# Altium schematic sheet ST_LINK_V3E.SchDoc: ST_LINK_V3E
size A3; Date: Not used; ApprovedBy: Not used; CheckedBy: Not used; Author: Not used; CompanyName: STMicroelectronics; DrawnBy: Not used; Engineer: Not used; Organization: Not used; Address1: Not used; Address2: Not used; Address3: Not used; Address4: Not used; DocumentNumber: Not used; Revision: Not used; SheetNumber: 10; SheetTotal: 12
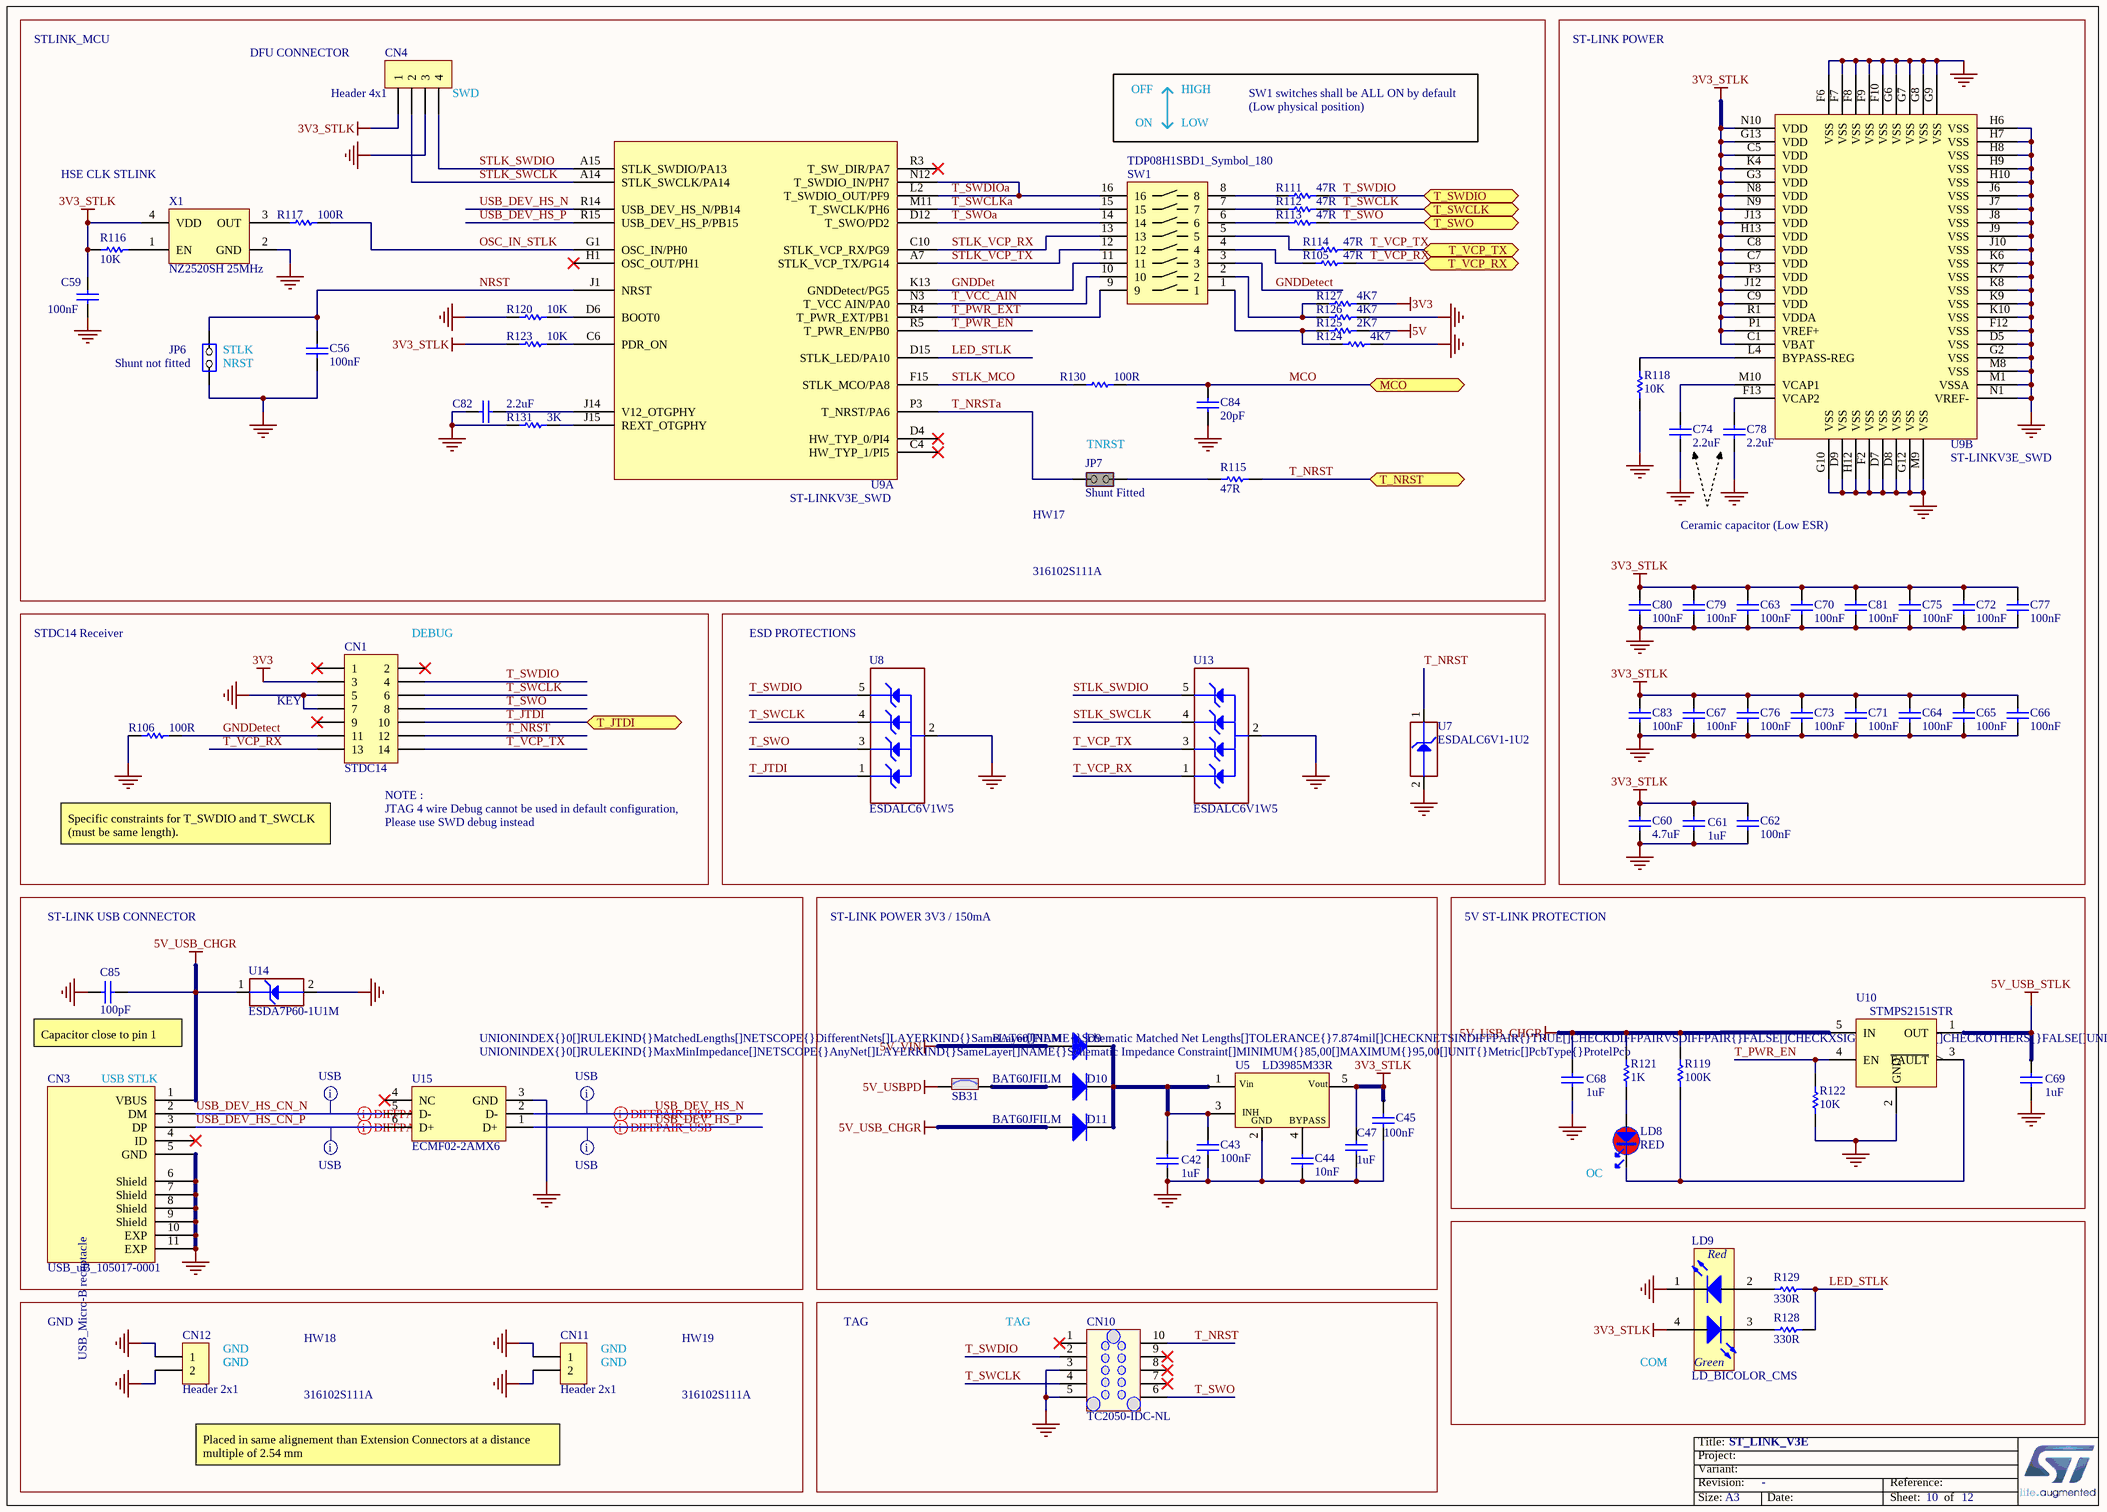
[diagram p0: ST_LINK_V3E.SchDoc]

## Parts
C42  value 1uF  [C0603]
C43  value 100nF  [C0402]
C44  value 10nF  [C0402]
C45  value 100nF  [C0402]
C47  value 1uF  [C0603]
C56  value 100nF  [C0402]
C59  value 100nF  [C0402]
C60  value 4.7uF  [C0603]
C61  value 1uF  [C0603]
C62  value 100nF  [C0402]
C63  value 100nF  [C0402]
C64  value 100nF  [C0402]
C65  value 100nF  [C0402]
C66  value 100nF  [C0402]
C67  value 100nF  [C0402]
C68  value 1uF  [C0603]
C69  value 1uF  [C0603]
C70  value 100nF  [C0402]
C71  value 100nF  [C0402]
C72  value 100nF  [C0402]
C73  value 100nF  [C0402]
C74  value 2.2uF  [C1206_H1P15]
C75  value 100nF  [C0402]
C76  value 100nF  [C0402]
C77  value 100nF  [C0402]
C78  value 2.2uF  [C1206_H1P15]
C79  value 100nF  [C0402]
C80  value 100nF  [C0402]
C81  value 100nF  [C0402]
C82  value 2.2uF  [C0603]
C83  value 100nF  [C0402]
C84  value 20pF  [C0402]
C85  value 100pF  [C0402]
CN1  value STDC14  [CON_STDC14_Receiver_MEDIUM]
CN3  value USB_uB_105017-0001  [CON_USBMICROB_MOLEX_105017-0001_H2P90]
CN4  value Header 4x1  [CON_SAMTEC_TSW-104-07-G-S]
CN10  value TC2050-IDC-NL  [CON_TAG-C_TC2050-IDC-NL]
CN11  Header 2x1  [CON_LYCONN_313102S141346]
CN12  Header 2x1  [CON_LYCONN_313102S141346]
D9  value BAT60JFILM  [DIO_SOD323]
D10  value BAT60JFILM  [DIO_SOD323]
D11  value BAT60JFILM  [DIO_SOD323]
HW17  value 316102S111A  (hidden comment: JUMPER_OPEN)
HW18  value 316102S111A  (hidden comment: JUMPER_OPEN)
HW19  value 316102S111A  (hidden comment: JUMPER_OPEN)
JP6  value Shunt not fitted  [CON_988-JIUBABA_313102S111116]  (hidden comment: Jumper_Header 2x1)
JP7  value Shunt Fitted  [CON_988-JIUBABA_313102S111116]  (hidden comment: Jumper_Header 2x1 Fitted)
LD8  value RED  [LED_0603_RED]
LD9  value LD_BICOLOR_CMS  [LED_BI-GR_HSMF-A201-A00J1]
R105  value 47R  [R0402]
R106  value 100R  [R0402]
R111  value 47R  [R0402]
R112  value 47R  [R0402]
R113  value 47R  [R0402]
R114  value 47R  [R0402]
R115  value 47R  [R0402]
R116  value 10K  [R0402]
R117  value 100R  [R0402]
R118  value 10K  [R0402]
R119  value 100K  [R0603]
R120  value 10K  [R0402]
R121  value 1K  [R0603]
R122  value 10K  [R0603]
R123  value 10K  [R0402]
R124  value 4K7  [R0402]
R125  value 2K7  [R0402]
R126  value 4K7  [R0402]
R127  value 4K7  [R0402]
R128  value 330R  [R0603]
R129  value 330R  [R0603]
R130  value 100R  [R0402]
R131  value 3K  [R0402]
SB31  SB_ON  [SOLDER-BRIDGE_R0603-0R]  (value not drawn)
SW1  value TDP08H1SBD1_Symbol_180  [SWI_C&K_TDP08H1SBD1]  (hidden comment: TDP08H1SBD1_180)
U5  value LD3985M33R  [REG_SOT23-5L]
U7  value ESDALC6V1-1U2  [ESD_ST0201]
U8  value ESDALC6V1W5  [ESD_SOT323-5L]
U9  value ST-LINKV3E_SWD  [ICC_UFBGA201_176+25_10X10_P065]  (parts A,B of 2)
U10  value STMPS2151STR  [MOS_SOT23-5L]
U13  value ESDALC6V1W5  [ESD_SOT323-5L]
U14  value ESDA7P60-1U1M  [ESD_QFN2_1P6X1_P125]
U15  value ECMF02-2AMX6  [ESD_QFN-6L_1P7X1P5_P050]
X1  value NZ2520SH 25MHz  [OSC_NDK_NZ2520SB_4P]  (hidden comment: OSCILLATOR_4_PINS)

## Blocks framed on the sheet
ESD PROTECTIONS: U7 U8 U13
ST-LINK POWER 3V3 / 150mA: C42-C45 C47 D9-D11 SB31 U5
COM: LD9 R128 R129

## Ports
MCO, T_JTDI, T_NRST, T_SWCLK, T_SWDIO, T_SWO, T_VCP_RX, T_VCP_TX

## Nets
3V3: CN1.3 R127.2
3V3_STLK: C45.2 C47.2 C59.2 C60.2 C61.2 C62.2 C63.2 C64.2 C65.2 C66.2 C67.2 C70.2 C71.2 C72.2 C73.2 C75.2 C76.2 C77.2 C79.2 C80.2 C81.2 C83.2 CN4.1 LD9.4(YellowGreen_anode) R116.1 R123.1 U5.5(Vout) U9.C1(VBAT) U9.C5(VDD) U9.C7(VDD) U9.C8(VDD) U9.C9(VDD) U9.F3(VDD) U9.G3(VDD) U9.G13(VDD) U9.H13(VDD) U9.J12(VDD) U9.J13(VDD) U9.K4(VDD) U9.N8(VDD) U9.N9(VDD) U9.N10(VDD) U9.P1(VREF+) U9.R1(VDDA) X1.4(VDD)
5V: R125.1
5V_USB_CHGR: C68.2 C85.2 CN3.1(VBUS) D11.1(A) R119.2 R121.2 U10.5(IN) U14.1(IO1)
5V_USB_STLK: C69.2 U10.1(OUT)
5V_USBPD: SB31.1
5V_VIN: D9.1(A)
GND: C42.1 C43.1 C44.1 C45.1 C47.1 C56.1 C59.1 C60.1 C61.1 C62.1 C63.1 C64.1 C65.1 C66.1 C67.1 C68.1 C69.1 C70.1 C71.1 C72.1 C73.1 C74.1 C75.1 C76.1 C77.1 C78.1 C79.1 C80.1 C81.1 C82.1 C83.1 C84.1 C85.1 CN1.5 CN1.7 CN3.5(GND) CN3.6(Shield) CN3.7(Shield) CN3.8(Shield) CN3.9(Shield) CN3.10(EXP) CN3.11(EXP) CN4.3 CN10.3 CN10.5 CN11.1 CN11.2 CN12.1 CN12.2 JP6.1(COMMON) LD9.1(RED_cathode) R106.1 R118.1 R120.1 R122.2 R124.1 R126.2 R131.1 U5.2(GND) U7.2(GND) U8.2(GND) U9.D5(VSS) U9.D7(VSS) U9.D8(VSS) U9.D9(VSS) U9.F2(VSS) U9.F6(VSS) U9.F7(VSS) U9.F8(VSS) U9.F9(VSS) U9.F10(VSS) U9.F12(VSS) U9.G2(VSS) U9.G6(VSS) U9.G7(VSS) U9.G8(VSS) U9.G9(VSS) U9.G10(VSS) U9.G12(VSS) U9.H6(VSS) U9.H7(VSS) U9.H8(VSS) U9.H9(VSS) U9.H10(VSS) U9.H12(VSS) U9.J6(VSS) U9.J7(VSS) U9.J8(VSS) U9.J9(VSS) U9.J10(VSS) U9.K6(VSS) U9.K7(VSS) U9.K8(VSS) U9.K9(VSS) U9.K10(VSS) U9.M1(VSSA) U9.M8(VSS) U9.M9(VSS) U9.N1(VREF-) U10.2(GND) U13.2(GND) U14.2(GND) U15.3(GND) X1.2(GND)
GNDDet: SW1.11 U9.K13(GNDDetect/PG5)
GNDDetect: CN1.11 R106.2 SW1.3
LED_STLK: R128.2 R129.2 U9.D15(STLK_LED/PA10)
MCO: C84.2 R130.2 ; port MCO
NRST: C56.2 JP6.2(NO) U9.J1(NRST)
OSC_IN_STLK: R117.2 U9.G1(OSC_IN/PH0)
STLK_MCO: R130.1 U9.F15(STLK_MCO/PA8)
STLK_SWCLK: CN4.2 U9.A14(STLK_SWCLK/PA14) U13.4(IO3)
STLK_SWDIO: CN4.4 U9.A15(STLK_SWDIO/PA13) U13.5(IO4)
STLK_VCP_RX: SW1.13 U9.C10(STLK_VCP_RX/PG9)
STLK_VCP_TX: SW1.12 U9.A7(STLK_VCP_TX/PG14)
T_JTDI: CN1.10 U8.1(IO1) ; port T_JTDI
T_NRST: CN1.12 CN10.10 R115.2 U7.1(IO1) ; port T_NRST
T_NRSTa: JP7.1(COMMON) U9.P3(T_NRST/PA6)
T_PWR_EN: R122.1 U9.R5(T_PWR_EN/PB0) U10.4(EN)
T_PWR_EXT: SW1.9 U9.R4(T_PWR_EXT/PB1)
T_SWCLK: CN1.6 CN10.4 R112.2 U8.4(IO3) ; port T_SWCLK
T_SWCLKa: SW1.15 U9.M11(T_SWCLK/PH6)
T_SWDIO: CN1.4 CN10.2 R111.2 U8.5(IO4) ; port T_SWDIO
T_SWDIOa: SW1.16 U9.L2(T_SWDIO_OUT/PF9) U9.N12(T_SWDIO_IN/PH7)
T_SWO: CN1.8 CN10.6 R113.2 U8.3(IO2) ; port T_SWO
T_SWOa: SW1.14 U9.D12(T_SWO/PD2)
T_VCC_AIN: SW1.10 U9.N3(T_VCC_AIN/PA0)
T_VCP_RX: CN1.13 R105.2 U13.1(IO1) ; port T_VCP_RX
T_VCP_TX: CN1.14 R114.2 U13.3(IO2) ; port T_VCP_TX
USB_DEV_HS_CN_N: CN3.2(DM) U15.5(D-)
USB_DEV_HS_CN_P: CN3.3(DP) U15.6(D+)
USB_DEV_HS_N: U9.R14(USB_DEV_HS_N/PB14) U15.2(D-)
USB_DEV_HS_P: U9.R15(USB_DEV_HS_P/PB15) U15.1(D+)
NetC42_2: C42.2 C43.2 D9.2(K) D10.2(K) D11.2(K) U5.1(Vin) U5.3(CE)
NetC44_2: C44.2 U5.4(BYPASS)
NetC74_2: C74.2 U9.M10(VCAP1)
NetC78_2: C78.2 U9.F13(VCAP2)
NetC82_2: C82.2 U9.J14(V12_OTGPHY)
NetD10_1: D10.1(A) SB31.2
NetJP7_2: JP7.2(NO) R115.1
NetLD8_1: LD8.1 R121.1
NetLD8_2: LD8.2 R119.1 U10.3(~{FAULT})
NetLD9_2: LD9.2(Red_anode) R129.1
NetLD9_3: LD9.3(YellowGreen_cathode) R128.1
NetR105_1: R105.1 SW1.4
NetR111_1: R111.1 SW1.8
NetR112_1: R112.1 SW1.7
NetR113_1: R113.1 SW1.6
NetR114_1: R114.1 SW1.5
NetR116_2: R116.2 X1.1(EN)
NetR117_1: R117.1 X1.3(OUT)
NetR118_2: R118.2 U9.L4(BYPASS-REG)
NetR120_2: R120.2 U9.D6(BOOT0)
NetR123_2: R123.2 U9.C6(PDR_ON)
NetR124_2: R124.2 R125.2 SW1.1
NetR126_1: R126.1 R127.1 SW1.2
NetR131_2: R131.2 U9.J15(REXT_OTGPHY)

Not connected (* = marked no-connect by the designer): CN1 1* 2* 9*; CN3 4(ID)*; CN10 1* 7* 8* 9*; U9 C4(HW_TYP_1/PI5)* D4(HW_TYP_0/PI4)* H1(OSC_OUT/PH1)* R3(T_SW_DIR/PA7)*; U15 4(NC)*

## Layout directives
differential pair; rule Impedance Constraint [Min = 85.00    Max = 95.00    ]: USB_DEV_HS_CN_N, USB_DEV_HS_CN_P, USB_DEV_HS_N, USB_DEV_HS_P
rule Undefined; rule Matched Net Lengths [Tolerance = 0.2mm]; rule Impedance Constraint [Min = 85.00    Max = 95.00    ]: USB_DEV_HS_CN_N, USB_DEV_HS_CN_P, USB_DEV_HS_N, USB_DEV_HS_P

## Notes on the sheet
- STLINK_MCU
- ST-LINK POWER
- DFU CONNECTOR
- (near CN4) SWD
- OFF
- HIGH
- SW1 switches shall be ALL ON by default
- (Low physical position)
- HSE CLK STLINK
- ON
- LOW
- (near JP6) STLK
- (near JP6) NRST
- (near JP7) TNRST
- Ceramic capacitor (Low ESR)
- STDC14 Receiver
- (near CN1) DEBUG
- (near CN1) KEY
- Specific constraints for T_SWDIO and T_SWCLK (must be same length).
- JTAG 4 wire Debug cannot be used in default configuration,
- Please use SWD debug instead
- (near CN1) NOTE :
- ST-LINK USB CONNECTOR
- 5V ST-LINK PROTECTION
- (near C85) Capacitor close to pin 1
- (near CN3) USB STLK
- (near LD8) OC
- GND
- TAG
- Placed in same alignement than Extension Connectors at a distance multiple of 2.54 mm

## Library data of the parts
C42 C47 C61 C68 C69 = MCD-00010: Capacitor, MLCC, 1uF, 16V, X5R, 10%, 0603, T=0,8mm; Manufacturer_Part_Number: CC0603KRX5R7BB105; Manufacturer: YAGEO; Provided_By: SUBCO
C43 C45 C56 C59 C62-C67 C70-C73 C75-C77 C79-C81 C83 = MCD-00102: Capacitor, MLCC, 100nF, 16V, X7R, 10%, 0402, T=0,5mm; Manufacturer_Part_Number: CC0402KRX7R7BB104; Manufacturer: YAGEO; Alternate_Manufacturer_Part_Number: GCM155R71C104KA55D; Alternate_Manufacturer: MURATA; Provided_By: SUBCO
C44 = MCD-00011: Capacitor, MLCC, 10nF, 16V, X7R, 10%, 0402, T=0.5mm; Manufacturer_Part_Number: CC0402KRX7R7BB103; Manufacturer: YAGEO; Provided_By: SUBCO
C60 = MCD-00009: Capacitor, MLCC, 4.7uF, 16V, X5R, 10%, 0603, T=0.8mm; Manufacturer_Part_Number: CC0603KRX5R7BB475; Manufacturer: YAGEO; Provided_By: SUBCO
C74 C78 = MCD-00008: Capacitor, MLCC, 2.2uF, 16V, X7R, 10%, 1206, T=1,15mm; Manufacturer_Part_Number: CC1206KKX7R7BB225; Manufacturer: YAGEO; Alternate_Manufacturer_Part_Number: C1206C225K4RAC; Alternate_Manufacturer: KEMET; Provided_By: SUBCO
C82 = MCD-00012: Capacitor, MLCC, 2.2uF, 10V, X5R, 10%, 0603, T=0,8mm; Manufacturer_Part_Number: CC0603KRX5R6BB225; Manufacturer: YAGEO; Alternate_Manufacturer_Part_Number: C0603C225K8PACTU; Alternate_Manufacturer: KEMET; Provided_By: SUBCO
C84 = MCD-00016: Capacitor, MLCC, 20pF, 50V, NPO, 5%, 0402, T=0,5mm; Manufacturer_Part_Number: CC0402JRNPO9BN200; Manufacturer: YAGEO; Provided_By: SUBCO
C85 = MCD-00205: Capacitor, MLCC, 100pF, 50V, NPO, 5%, 0402, T=0,5mm; Manufacturer_Part_Number: CC0402JRNPO9BN101; Manufacturer: YAGEO; Provided_By: SUBCO
CN1 = MCD-00592: Header 7x2, 1.27mm, Dual row, Straight, "STDC14_MEDIUM" : footprint compatible with FTSH-107-01-L-DV,-K,-A,-P,-ES (use "STDC14_BIG" to also be compatible with SHF-107-01-L-D-SM,-K); Part_Type: Connector; Manufacturer_Part_Number: FTSH-107-01-L-DV-K; Manufacturer: SAMTEC; Provided_By: SUBCO
CN3 = MCD-00028: USB-MICRO-B, 0.65mm, RA, SMT, Bottom Mount,; Manufacturer_Part_Number: 1050170001; Manufacturer: MOLEX; Part_Type: Connector; Provided_By: SUBCO
CN4 = MCD-00029: Header, 4x1, 2,54mm, VR, TH, Height 5.84mm/2.54mm; Manufacturer_Part_Number: TSW-104-07-x-S; Manufacturer: SAMTEC; Part_Type: Connector; Provided_By: SUBCO
CN10 = MCD-00031: Tag_Connector Header, 10x2, No legs; Manufacturer_Part_Number: TC2050-IDC-NL-FP; Manufacturer: TAG-CONNECT LLC; Provided_By: SUBCO
CN11 CN12 = MCD-01668: Header 2x1, 2.54mm, VR, TH, height 5.84mm/5.08 mm, height total 13.46 mm; Part_Type: Connector; Manufacturer_Part_Number: 313102S141346; Manufacturer: LYCONN; Provided_By: SUBCO
D9-D11 = MCD-00034: BAT60JFILM; Manufacturer: STMICROELECTRONICS; Part_Type: Diode; BMS_Part_Number: 9151097; Provided_By: SUBCO with ST control
HW17-HW19 = MCD-01849: Jumper, height 6mm, Black, 2.54mm, 3A, 20 mohm, open; Part_Type: Mechanical; Manufacturer: JIUBABA; Provided_By: SUBCO
JP6 = MCD-01660: Header 2x1, 2.54mm, VR, TH, height 6 mm / 3 mm, total 11.6mm - Shunt not Fitted by default; Part_Type: Connector; Manufacturer_Part_Number: 313102S111116; Manufacturer: JIUBABA; Provided_By: SUBCO
JP7 = MCD-01662: Header 2x1, 2.54mm, VR, TH, height 6 mm / 3 mm, total 11.6mm - Shunt Fitted by default; Part_Type: Connector; Manufacturer_Part_Number: 313102S111116; Manufacturer: JIUBABA; Provided_By: SUBCO
LD8 = MCD-00049: LED, Red, 0603; Manufacturer_Part_Number: 19-213-R6C-AP1Q2B/3T; Manufacturer: EVERLIGHT; Part_Type: Display; Provided_By: SUBCO
LD9 = MCD-00051: LED Bicolor; Part_Type: Display; Manufacturer_Part_Number: HSMF-A201-A00J1; Manufacturer: AVAGO TECHNOLOGIES; Alternate_Manufacturer_Part_Number: LE-RGW35280; Alternate_Manufacturer: EVERLUCK; Provided_By: SUBCO
R105 R111-R115 = MCD-00481: Resistor,47R,0402,1%,1/16W; Manufacturer_Part_Number: RC0402FR-0747RL; Manufacturer: YAGEO; Provided_By: SUBCO
R106 R117 R130 = MCD-00119: Resistor,100R,0402,1%,1/16W; Manufacturer_Part_Number: RC0402FR-07100RL; Manufacturer: YAGEO; Provided_By: SUBCO
R116 R118 R120 R123 = MCD-00053: Resistor,10K,0402,1%,1/16W; Manufacturer_Part_Number: RC0402FR-0710KL; Manufacturer: YAGEO; Provided_By: SUBCO
R119 = MCD-00223: Resistor,100K,0603,1%,1/10W; Manufacturer_Part_Number: RC0603FR-07100KL; Manufacturer: YAGEO; Provided_By: SUBCO
R121 = MCD-00070: Resistor,1K,0603,1%,1/10W; Manufacturer_Part_Number: RC0603FR-071KL; Manufacturer: YAGEO; Provided_By: SUBCO
R122 = MCD-00220: Resistor,10K,0603,1%,1/10W; Manufacturer_Part_Number: RC0603FR-0710KL; Manufacturer: YAGEO; Provided_By: SUBCO
R124 R126 R127 = MCD-00065: Resistor,4K7,0402,1%,1/16W; Manufacturer_Part_Number: RC0402FR-074K7L; Manufacturer: YAGEO; Alternate_Manufacturer_Part_Number: RT0402FRE074K7L; Provided_By: SUBCO
R125 = MCD-00055: Resistor,2K7,0402,1%,1/16W; Manufacturer_Part_Number: RC0402FR-072K7L; Manufacturer: YAGEO; Provided_By: SUBCO
R128 R129 = MCD-00197: Resistor,330R,0603,1%,1/10W; Manufacturer_Part_Number: RC0603FR-07330RL; Manufacturer: YAGEO; BMS_Part_Number: 9129729; Provided_By: SUBCO
R131 = MCD-00185: Resistor,3K,0402,1%,1/16W; Manufacturer_Part_Number: RC0402FR-073KL; Manufacturer: YAGEO; Provided_By: SUBCO
SB31 = MCD-00071: Solder Bridge ON; Part_Type: Mechanical; Manufacturer_Part_Number: RC0603JR-070RL; Manufacturer: YAGEO; Provided_By: SUBCO
SW1 = MCD-01685: 8 positions, Side Actuated DIP switch, 1.27mm, SMT, height 4.1mm, piano type; Part_Type: Misc; Manufacturer: C&K; Provided_By: SUBCO
U5 = MCD-00086: Ultra low drop-low noise BiCMOS voltage, regulators low ESR capacitors compatible; Manufacturer: STMICROELECTRONICS; Part_Type: IC; BMS_Part_Number: 9176161; Provided_By: SUBCO with ST control
U7 = MCD-00170: ESD protection 6V1; Part_Type: Diode; Manufacturer: STMICROELECTRONICS; BMS_Part_Number: 9151132; Provided_By: SUBCO with ST control
U8 U13 = MCD-00136: Dual Transil array for ESD protection; Part_Type: Diode; Manufacturer: STMICROELECTRONICS; BMS_Part_Number: 9151112; Provided_By: SUBCO with ST control
U9 = MCD-00596: STM32F723IEK  (STM32F7) BGA176; Part_Type: IC; Manufacturer_Part_Number: STM32F723IEK6; Manufacturer: STMICROELECTRONICS; BMS_Part_Number: 9175300; Provided_By: SUBCO with ST control
U10 = MCD-00159: 500mA, Enhanced single channel power switches with active high enable pin; Part_Type: IC; Manufacturer: STMICROELECTRONICS; Alternate_Manufacturer_Part_Number: TPS2051C; Alternate_Manufacturer: TEXAS INSTRUMENTS; BMS_Part_Number: 9159009; Provided_By: SUBCO with ST control
U14 = MCD-00251: High power transient voltage suppressor, 7V breakdown; Part_Type: Diode; Manufacturer: STMICROELECTRONICS; BMS_Part_Number: 9179042; Provided_By: SUBCO with ST control
U15 = MCD-00649: Common mode filter with ESD protection for USB 2.0 interface; Part_Type: Diode; Manufacturer: STMICROELECTRONICS; BMS_Part_Number: 9151138; Provided_By: SUBCO with ST control
X1 = MCD-00597: Oscillator 25Mhz, +-50ppm, Vcc:3.3V typ, square wave: [0.1Vcc;0.9Vcc], Enable pin, SMD; Part_Type: Crystal_Osc; Manufacturer_Part_Number: NZ2520SH 25MHz END4869C; Manufacturer: NDK; Alternate_Manufacturer_Part_Number: NZ2520SB 25MHz END4869B; BMS_Part_Number: 9157050; Provided_By: SUBCO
